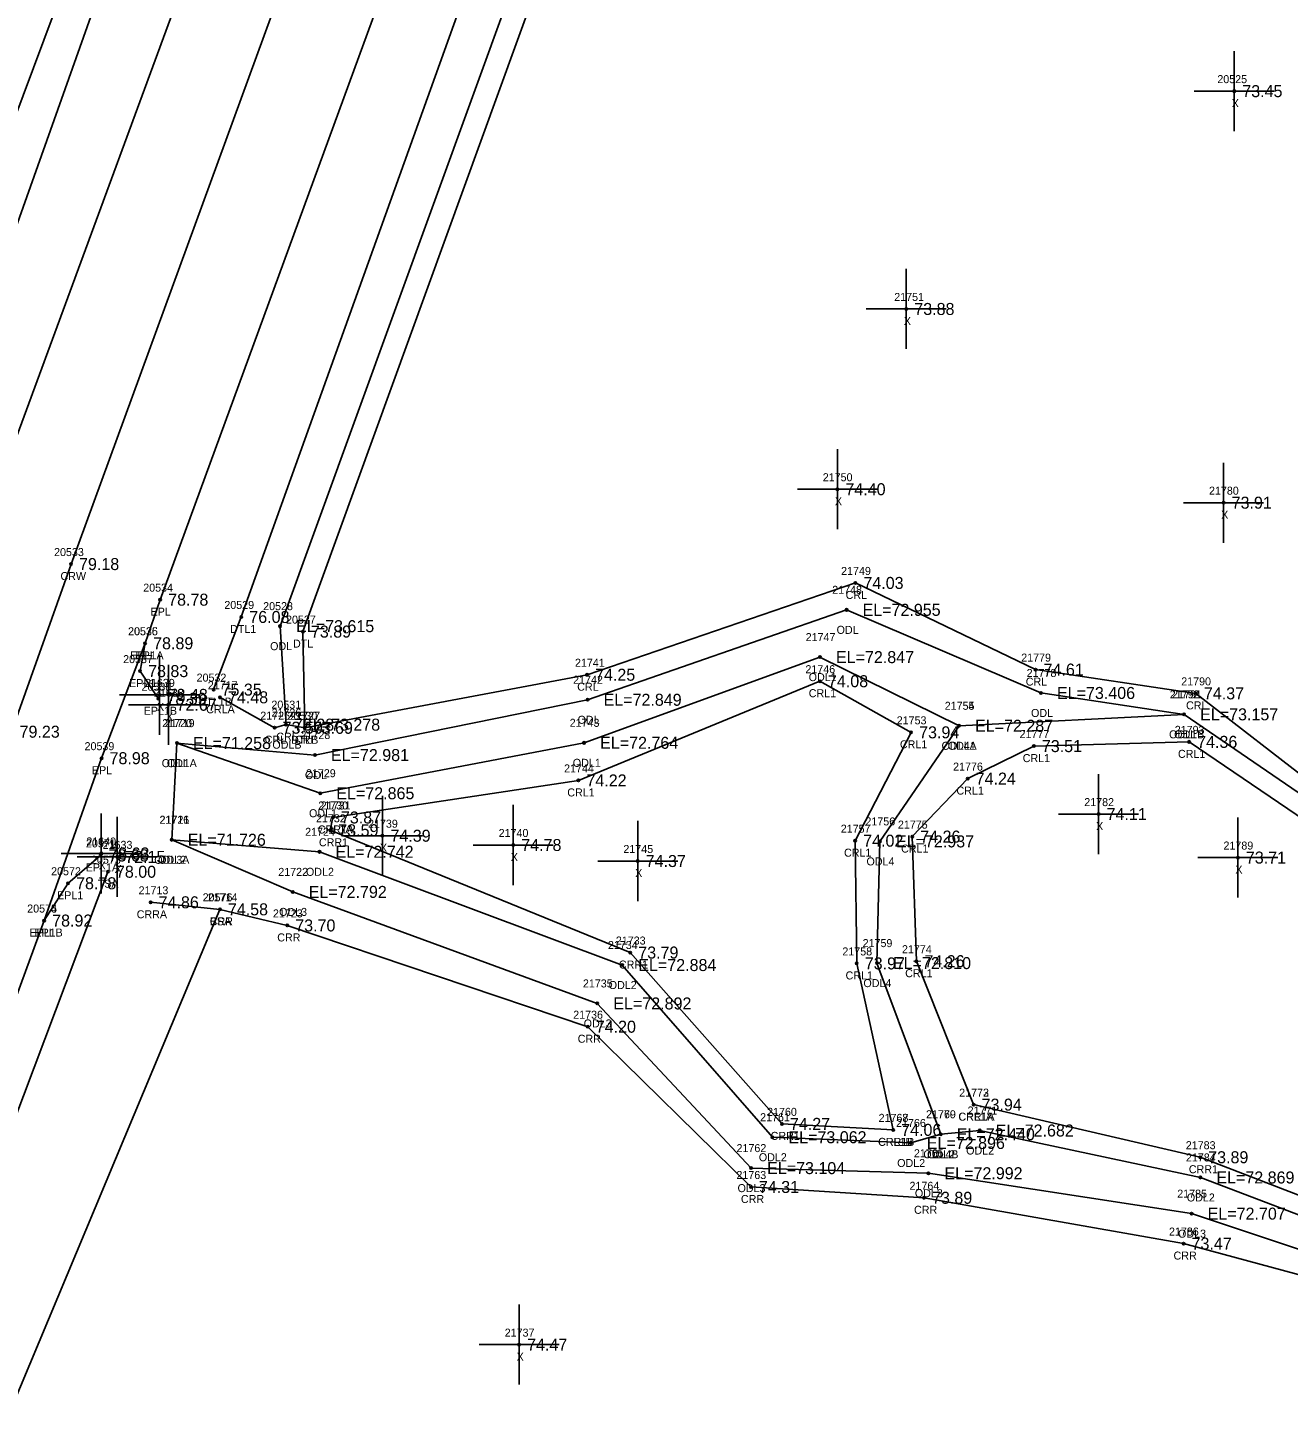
# Model space of a CAD drawing. Extents: x 2140110 to 2141565, y 506241 to 510327.
# Drawn here: x 2140964.5 to 2141122, y 508982.3 to 509154.8 of the extents above; entities that cross this region are included whole.
import ezdxf

# ---------------------------------------------------------------- set-up
doc = ezdxf.new("R2010")
doc.units = 0
for name, color, linetype in [('RD_DTM_BkLn1', 7, 'Continuous'), ('RD_DTM_BkLn2', 7, 'Continuous'), ('RD_DTM_BkLn_txCode', 7, 'Continuous'), ('RD_EX_H2O', 7, 'Continuous'), ('RD_EX_H2O_txCode', 7, 'Continuous'), ('RD_EX_Misc', 7, 'Continuous'), ('RD_EX_Misc_txCode', 7, 'Continuous'), ('RD_EX_Road', 7, 'Continuous'), ('RD_EX_Road_txCode', 7, 'Continuous'), ('RD_EX_TX_H2O_ELEV', 7, 'Continuous'), ('RD_EX_TX_Misc_ELEV', 7, 'Continuous'), ('RD_EX_TX_Road_ELEV', 7, 'Continuous'), ('RD_HC_Survey_ELEV', 7, 'Continuous'), ('RD_HC_Survey_txCode', 7, 'Continuous'), ('RD_SMD_Locator', 7, 'Continuous')]:
    doc.layers.add(name, color=color, linetype=linetype)

msp = doc.modelspace()

# ---------------------------------------------------------------- linework, layer by layer
at = {"layer": 'RD_DTM_BkLn1'}
msp.add_lwpolyline([(2141401.24, 510292.17), (2141386.62, 510241.55), (2141370.29, 510189.18), (2141352.34, 510135.64), (2141334.07, 510083.82), (2141314.82, 510031.25), (2141297.4, 509983.45), (2141260.01, 509880.66), (2141224.45, 509783.3), (2141187.1, 509681.41), (2141150.45, 509581.24), (2141112.96, 509478.26), (2141074.89, 509374.78), (2141038.89, 509276.46), (2141003.79, 509180.59), (2140969.89, 509087.8), (2140962.46, 509066.85), (2140921.91, 508956.12), (2140885.66, 508857.72), (2140850.55, 508762.05)], dxfattribs=at)
at = {"layer": 'RD_DTM_BkLn2'}
for points in [[(2140974.5, 509049.35), (2140937.76, 508951.84), (2140901.13, 508851.11), (2140867.71, 508755.37), (2140831.32, 508652.9), (2140795.63, 508558.35), (2140771.77, 508494.7), (2140759.99, 508454.23), (2140734.05, 508387.83)], [(2140988.49, 509044.65), (2140947.93, 508947.73), (2140912.71, 508846.53), (2140877.42, 508750.71), (2140841.6, 508647.73), (2140806.94, 508554.43), (2140782.47, 508491.27), (2140767.03, 508451.8), (2140743.6, 508391.1), (2140740.93, 508386.48)]]:
    msp.add_lwpolyline(points, dxfattribs=at)
at = {"layer": 'RD_EX_H2O'}
for points in [[(2141109.57, 509415.73), (2141114.37, 509420.62), (2141120.58, 509418.47), (2141123.73, 509414.72), (2141106.65, 509363.28), (2141087.87, 509318.68), (2141079.16, 509303.21), (2141069.29, 509273.89), (2141065.76, 509268.54), (2141032.31, 509171.57), (2140998.87, 509079.36), (2140999.1, 509067.34)], [(2141109.57, 509415.73), (2141094.19, 509368.74), (2141059.48, 509270.33), (2141024.5, 509174.17), (2140991.17, 509081.19), (2140987.7, 509072.11)], [(2141117.74, 509414.57), (2141100.21, 509366.33), (2141064.01, 509269.32), (2141029.63, 509172.59), (2140996.02, 509080.04), (2140996.76, 509067.73)], [(2141025.18, 509330), (2141033.42, 509326.19), (2141034.03, 509320.6), (2141020.74, 509281.87), (2140983.57, 509187.83), (2140949.44, 509091.79), (2140950.12, 509084.29)], [(2141028.31, 509323.95), (2141015.1, 509284.32), (2140979.54, 509188.24), (2140943.06, 509090.7)], [(2140988.5, 509071.15), (2140995.33, 509067.35), (2140996.76, 509067.73), (2140999.1, 509067.34), (2141034.38, 509073.97), (2141067.92, 509085.44), (2141090.44, 509074.61), (2141110.47, 509071.64), (2141125.77, 509059.81), (2141130.36, 509054.36)], [(2140983.12, 509065.42), (2141000.37, 509063.93), (2141034.44, 509070.84), (2141066.81, 509082.08), (2141091.11, 509071.69), (2141109, 509069.02), (2141130.36, 509054.36)], [(2140983.12, 509065.42), (2141001.04, 509059.16), (2141034.01, 509065.46), (2141063.49, 509076.17), (2141080.87, 509067.59), (2141109, 509069.02)], [(2141002.62, 509056.13), (2141033.3, 509060.76), (2141063.49, 509073.16), (2141074.88, 509066.77), (2141067.89, 509053.23), (2141068.09, 509037.89), (2141072.64, 509017.09)], [(2141080.87, 509067.59), (2141070.99, 509053.14), (2141070.61, 509037.93), (2141078.58, 509016.54)], [(2140983.12, 509065.42), (2140982.47, 509053.34), (2141000.94, 509051.84), (2141038.78, 509037.69), (2141057.55, 509016.17), (2141074.84, 509015.45), (2141078.58, 509016.54), (2141083.45, 509017.01), (2141111.03, 509011.14), (2141158.09, 508993.23), (2141163.15, 508993.34), (2141185.07, 509013.58), (2141188.28, 509016.58)], [(2141082.69, 509020.24), (2141075.54, 509038.17), (2141075.02, 509053.74), (2141081.95, 509060.99), (2141090.22, 509065.05), (2141109.63, 509065.58), (2141124.15, 509055.72), (2141130.36, 509054.36)], [(2141002.62, 509056.13), (2141002.29, 509054.53), (2141039.78, 509039.25), (2141058.74, 509017.84), (2141072.64, 509017.09)], [(2140982.47, 509053.34), (2140997.59, 509046.83), (2141035.66, 509032.89), (2141054.88, 509012.31), (2141077.05, 509011.67), (2141109.94, 509006.62), (2141157.44, 508990.81), (2141163.15, 508993.34)], [(2140979.84, 509045.53), (2140988.49, 509044.65), (2140996.91, 509042.64), (2141034.47, 509029.98), (2141054.86, 509009.95), (2141076.5, 509008.6), (2141108.93, 509002.88), (2141157.17, 508989.85), (2141167.48, 508991.01), (2141188.81, 509012.46), (2141188.28, 509016.58)], [(2141082.69, 509020.24), (2141111.01, 509013.67), (2141158.94, 508995.2), (2141180.37, 509014.56), (2141188.28, 509016.58)]]:
    msp.add_lwpolyline(points, dxfattribs=at)
at = {"layer": 'RD_EX_Misc'}
for p, q in [((2141115.27, 509141.9), (2141115.27, 509151.9)), ((2141110.27, 509146.9), (2141120.27, 509146.9)), ((2141074.28, 509114.68), (2141074.28, 509124.68)), ((2141069.28, 509119.68), (2141079.28, 509119.68)), ((2141065.67, 509092.15), (2141065.67, 509102.15)), ((2141113.94, 509090.47), (2141113.94, 509100.47)), ((2141060.67, 509097.15), (2141070.67, 509097.15)), ((2141108.94, 509095.47), (2141118.94, 509095.47)), ((2140980.96, 509066.45), (2140980.96, 509076.45)), ((2140982.07, 509065.22), (2140982.07, 509075.22)), ((2140975.96, 509071.45), (2140985.96, 509071.45)), ((2140977.07, 509070.22), (2140987.07, 509070.22)), ((2141098.31, 509051.55), (2141098.31, 509061.55)), ((2141008.81, 509048.85), (2141008.81, 509058.85)), ((2141025.16, 509047.69), (2141025.16, 509057.69)), ((2140973.66, 509046.63), (2140973.66, 509056.63)), ((2140975.66, 509046.21), (2140975.66, 509056.21)), ((2141093.31, 509056.55), (2141103.31, 509056.55)), ((2141115.72, 509046.12), (2141115.72, 509056.12)), ((2141040.71, 509045.69), (2141040.71, 509055.69)), ((2141003.81, 509053.85), (2141013.81, 509053.85)), ((2141020.16, 509052.69), (2141030.16, 509052.69)), ((2140968.66, 509051.63), (2140978.66, 509051.63)), ((2140970.66, 509051.21), (2140980.66, 509051.21)), ((2141110.72, 509051.12), (2141120.72, 509051.12)), ((2141035.71, 509050.69), (2141045.71, 509050.69)), ((2141025.89, 508985.25), (2141025.89, 508995.25)), ((2141020.89, 508990.25), (2141030.89, 508990.25))]:
    msp.add_line(p, q, dxfattribs=at)
at = {"layer": 'RD_EX_Road'}
for points in [[(2141175.93, 509686.04), (2141140.09, 509588.3), (2141106.08, 509494.11), (2141096.82, 509469.24), (2141063.82, 509378.98), (2141052.52, 509348.48), (2141043.48, 509323.88), (2141027.84, 509280.54), (2140992.95, 509184.87), (2140958.53, 509091.45), (2140950.8, 509069.47), (2140944.28, 509052.06), (2140911.45, 508962.1), (2140874.65, 508861.6), (2140839.42, 508765.22), (2140802.38, 508664.56)], [(2141197.99, 509676.56), (2141193.66, 509664.6), (2141161.61, 509577.24), (2141123.75, 509473.61), (2141115.5, 509450.65), (2141102.09, 509414.61), (2141086.27, 509371.27), (2141050.42, 509272.83), (2141015.08, 509176.39), (2140981.03, 509083.35), (2140979.15, 509077.9), (2140973.7, 509063.54), (2140966.53, 509043.25), (2140933.44, 508952.99), (2140896.92, 508852.59), (2140862.18, 508757.77)], [(2140979.15, 509077.9), (2140978.52, 509074.42), (2140980.81, 509070.97)], [(2140973.58, 509051.39), (2140969.52, 509047.91), (2140966.53, 509043.25)]]:
    msp.add_lwpolyline(points, dxfattribs=at)
at = {"layer": 'RD_SMD_Locator'}
for centre in [(2141115.27, 509146.9), (2141074.28, 509119.68), (2141065.67, 509097.15), (2141113.94, 509095.47), (2140969.89, 509087.8), (2141067.92, 509085.44), (2140981.03, 509083.35), (2141066.81, 509082.08), (2140991.17, 509081.19), (2140996.02, 509080.04), (2140998.87, 509079.36), (2140979.15, 509077.9), (2140979.15, 509077.9), (2141063.49, 509076.17), (2140978.52, 509074.42), (2141034.38, 509073.97), (2141063.49, 509073.16), (2141090.44, 509074.61), (2140980.96, 509071.45), (2140987.7, 509072.11), (2141091.11, 509071.69), (2141110.47, 509071.64), (2140980.81, 509070.97), (2140982.07, 509070.22), (2140988.5, 509071.15), (2141034.44, 509070.84), (2141109, 509069.02), (2141109, 509069.02), (2140995.33, 509067.35), (2140996.76, 509067.73), (2140996.76, 509067.73), (2140999.1, 509067.34), (2140999.1, 509067.34), (2141074.88, 509066.77), (2141080.87, 509067.59), (2141080.87, 509067.59), (2140983.12, 509065.42), (2140983.12, 509065.42), (2141034.01, 509065.46), (2141090.22, 509065.05), (2141109.63, 509065.58), (2140973.7, 509063.54), (2141000.37, 509063.93), (2141081.95, 509060.99), (2141033.3, 509060.76), (2141001.04, 509059.16), (2141002.62, 509056.13), (2141002.62, 509056.13), (2141098.31, 509056.55), (2141002.29, 509054.53), (2140982.47, 509053.34), (2140982.47, 509053.34), (2141008.81, 509053.85), (2141025.16, 509052.69), (2141067.89, 509053.23), (2141070.99, 509053.14), (2141075.02, 509053.74), (2140973.58, 509051.39), (2140973.66, 509051.63), (2140975.66, 509051.21), (2141000.94, 509051.84), (2141040.71, 509050.69), (2141115.72, 509051.12), (2140974.5, 509049.35), (2140969.52, 509047.91), (2140979.84, 509045.53), (2140997.59, 509046.83), (2140988.49, 509044.65), (2140988.49, 509044.65), (2140966.53, 509043.25), (2140966.53, 509043.25), (2140996.91, 509042.64), (2141039.78, 509039.25), (2141038.78, 509037.69), (2141068.09, 509037.89), (2141070.61, 509037.93), (2141075.54, 509038.17), (2141035.66, 509032.89), (2141034.47, 509029.98), (2141082.69, 509020.24), (2141082.69, 509020.24), (2141058.74, 509017.84), (2141057.55, 509016.17), (2141072.64, 509017.09), (2141072.64, 509017.09), (2141078.58, 509016.54), (2141078.58, 509016.54), (2141083.45, 509017.01), (2141074.84, 509015.45), (2141111.01, 509013.67), (2141054.88, 509012.31), (2141077.05, 509011.67), (2141111.03, 509011.14), (2141054.86, 509009.95), (2141076.5, 509008.6), (2141109.94, 509006.62), (2141108.93, 509002.88), (2141025.89, 508990.25)]:
    msp.add_circle(centre, 0.15, dxfattribs=at)

# ---------------------------------------------------------------- texts
at = {"layer": 'RD_DTM_BkLn_txCode'}
for s, p in [('20573', (2140972.38, 509050.35)), ('TSA', (2140973.22, 509047.35)), ('20576', (2140986.34, 509045.65)), ('BSA', (2140987.22, 509042.65))]:
    msp.add_text(s, height=1, dxfattribs=at).set_placement(p)
at = {"layer": 'RD_EX_H2O_txCode'}
for s, p in [('21749', (2141066.13, 509086.44)), ('21748', (2141065.02, 509084.08)), ('CRL', (2141066.7, 509083.44)), ('20529', (2140989.05, 509082.19)), ('20528', (2140993.9, 509082.04)), ('DTL1', (2140989.76, 509079.19)), ('20527', (2140996.76, 509080.36)), ('ODL', (2141065.57, 509079.08)), ('DTL', (2140997.63, 509077.36)), ('21747', (2141061.7, 509078.17)), ('ODL', (2140994.77, 509077.04)), ('21779', (2141088.64, 509075.61)), ('21741', (2141032.87, 509074.97)), ('21746', (2141061.67, 509074.16)), ('20532', (2140985.58, 509073.11)), ('21717', (2140986.98, 509072.15)), ('21742', (2141032.64, 509072.84)), ('ODL1', (2141062.08, 509073.17)), ('CRL', (2141089.21, 509072.61)), ('21778', (2141089.32, 509073.69)), ('21790', (2141108.64, 509072.64)), ('CRL', (2141033.15, 509071.97)), ('CRL1', (2141062.09, 509071.16)), ('21792', (2141107.21, 509071.02)), ('21791', (2141107.49, 509071.02)), ('DTL1B', (2140985.82, 509070.11)), ('CRLA', (2140986.78, 509069.15)), ('20531', (2140994.93, 509069.73)), ('21726', (2140994.95, 509068.73)), ('21754', (2141079.08, 509069.59)), ('21755', (2141079.08, 509069.59)), ('CRL', (2141109.24, 509069.64)), ('21720', (2140981.28, 509067.42)), ('21719', (2140981.61, 509067.42)), ('21725', (2140993.54, 509068.35)), ('20530', (2140996.94, 509068.34)), ('21727', (2140997.3, 509068.34)), ('21743', (2141032.21, 509067.46)), ('ODL', (2141033.2, 509067.84)), ('21753', (2141073.08, 509067.77)), ('ODL', (2141089.87, 509068.69)), ('CRL', (2140994.1, 509065.35)), ('CRL', (2140995.54, 509065.73)), ('DTLB', (2140997.38, 509065.34)), ('CRL', (2140997.87, 509065.34)), ('21728', (2140998.57, 509065.93)), ('21777', (2141088.43, 509066.05)), ('ODL1B', (2141107.12, 509066.02)), ('ODL', (2141107.76, 509066.02)), ('21793', (2141107.83, 509066.58)), ('ODLB', (2140995.05, 509064.73)), ('CRL1', (2141073.48, 509064.77)), ('ODL4A', (2141078.69, 509064.59)), ('ODL1', (2141079.47, 509064.59)), ('CRL1', (2141108.23, 509063.58)), ('ODL1A', (2140981.22, 509062.42)), ('ODL', (2140981.87, 509062.42)), ('ODL1', (2141032.6, 509062.46)), ('21776', (2141080.13, 509061.99)), ('CRL1', (2141088.83, 509063.05)), ('ODL', (2140999.12, 509060.93)), ('21729', (2140999.25, 509061.16)), ('21744', (2141031.51, 509061.76)), ('CRL1', (2141031.91, 509058.76)), ('CRL1', (2141080.55, 509058.99)), ('21730', (2141000.79, 509057.13)), ('21731', (2141001.11, 509057.13)), ('21716', (2140980.93, 509055.34)), ('21721', (2140980.96, 509055.34)), ('ODL1', (2140999.63, 509056.16)), ('21732', (2141000.5, 509055.53)), ('21756', (2141069.17, 509055.14)), ('21724', (2140999.15, 509053.84)), ('CRR1A', (2141000.72, 509054.13)), ('CRL1A', (2141000.74, 509054.13)), ('21757', (2141066.09, 509054.23)), ('21775', (2141073.23, 509054.74)), ('CRR1', (2141000.87, 509052.53)), ('CRL1', (2141073.63, 509051.74)), ('ODL3A', (2140980.29, 509050.34)), ('ODL2', (2140980.78, 509050.34)), ('CRL1', (2141066.5, 509051.23)), ('ODL4', (2141069.3, 509050.14)), ('21722', (2140995.79, 509048.83)), ('ODL2', (2140999.25, 509048.84)), ('21713', (2140978.33, 509046.53)), ('21714', (2140986.97, 509045.65)), ('CRRA', (2140978.1, 509043.53)), ('21723', (2140995.12, 509043.64)), ('ODL3', (2140995.89, 509043.83)), ('CRR', (2140987.23, 509042.65)), ('CRR', (2140995.66, 509040.64)), ('21734', (2141036.99, 509039.69)), ('21733', (2141037.98, 509040.25)), ('21759', (2141068.82, 509039.93)), ('21758', (2141066.29, 509038.89)), ('21774', (2141073.74, 509039.17)), ('CRR1', (2141038.36, 509037.25)), ('CRL1', (2141074.14, 509036.17)), ('21735', (2141033.86, 509034.89)), ('ODL2', (2141037.09, 509034.69)), ('CRL1', (2141066.69, 509035.89)), ('ODL4', (2141068.92, 509034.93)), ('21736', (2141032.65, 509030.98)), ('ODL3', (2141033.96, 509029.89)), ('CRR', (2141033.21, 509027.98)), ('21772', (2141080.89, 509021.24)), ('21773', (2141080.89, 509021.24)), ('21760', (2141056.88, 509018.84)), ('21771', (2141081.94, 509019.01)), ('21761', (2141056.01, 509018.17)), ('21767', (2141070.82, 509018.09)), ('21768', (2141070.82, 509018.09)), ('21766', (2141073, 509017.45)), ('21770', (2141076.74, 509018.54)), ('21769', (2141076.76, 509018.54)), ('CRR1A', (2141080.78, 509018.24)), ('CRL1A', (2141080.81, 509018.24)), ('CRR1', (2141057.32, 509015.84)), ('21762', (2141053.06, 509014.31)), ('CRR1B', (2141070.75, 509015.09)), ('CRL1B', (2141070.77, 509015.09)), ('21765', (2141075.23, 509013.67)), ('ODL4B', (2141076.41, 509013.54)), ('ODL2', (2141076.88, 509013.54)), ('ODL2', (2141081.76, 509014.01)), ('21783', (2141109.21, 509014.67)), ('ODL2', (2141055.85, 509013.17)), ('ODL2', (2141073.14, 509012.45)), ('21784', (2141109.23, 509013.14)), ('21763', (2141053.05, 509010.95)), ('CRR1', (2141109.59, 509011.67)), ('ODL3', (2141053.19, 509009.31)), ('21764', (2141074.68, 509009.6)), ('ODL3', (2141075.35, 509008.67)), ('21785', (2141108.14, 509008.62)), ('CRR', (2141053.61, 509007.95)), ('CRR', (2141075.25, 509006.6)), ('ODL2', (2141109.34, 509008.14)), ('21786', (2141107.11, 509003.88)), ('ODL3', (2141108.24, 509003.62)), ('CRR', (2141107.68, 509000.88))]:
    msp.add_text(s, height=1, dxfattribs=at).set_placement(p)
at = {"layer": 'RD_EX_Misc_txCode'}
for s, p in [('20525', (2141113.15, 509147.9)), ('X', (2141114.95, 509144.9)), ('21751', (2141072.77, 509120.68)), ('X', (2141073.97, 509117.68)), ('21750', (2141063.84, 509098.15)), ('21780', (2141112.11, 509096.47)), ('X', (2141065.36, 509095.15)), ('X', (2141113.63, 509093.47)), ('21639', (2140979.14, 509072.45)), ('21638', (2140980.25, 509071.22)), ('X', (2140980.64, 509069.45)), ('X', (2140981.75, 509068.22)), ('21782', (2141096.52, 509057.55)), ('21739', (2141007.01, 509054.85)), ('21740', (2141023.33, 509053.69)), ('X', (2141098, 509054.55)), ('21640', (2140971.8, 509052.63)), ('21633', (2140973.84, 509052.21)), ('X', (2141008.49, 509051.85)), ('21745', (2141038.92, 509051.69)), ('21789', (2141113.92, 509052.12)), ('X', (2141024.85, 509050.69)), ('X', (2140973.34, 509049.63)), ('X', (2140975.34, 509049.21)), ('X', (2141040.4, 509048.69)), ('X', (2141115.4, 509049.12)), ('21737', (2141024.09, 508991.25)), ('X', (2141025.58, 508988.25))]:
    msp.add_text(s, height=1, dxfattribs=at).set_placement(p)
at = {"layer": 'RD_EX_Road_txCode'}
for s, p in [('20534', (2140978.91, 509084.35)), ('EPL', (2140979.83, 509081.35)), ('20536', (2140977.01, 509078.9)), ('20535', (2140977.03, 509078.9)), ('EPL1A', (2140977.29, 509075.9)), ('EPL', (2140977.95, 509075.9)), ('20537', (2140976.4, 509075.42)), ('EPL1', (2140977.15, 509072.42)), ('20538', (2140978.7, 509071.97)), ('EPL1B', (2140978.97, 509068.97)), ('20539', (2140971.58, 509064.54)), ('EPL', (2140972.5, 509061.54)), ('20571', (2140971.75, 509052.39)), ('20572', (2140967.4, 509048.91)), ('EPL1A', (2140971.73, 509049.39)), ('EPL1', (2140968.15, 509045.91)), ('20574', (2140964.41, 509044.25)), ('20575', (2140964.41, 509044.25)), ('EPL1B', (2140964.69, 509041.25)), ('EPL', (2140965.32, 509041.25))]:
    msp.add_text(s, height=1, dxfattribs=at).set_placement(p)
at = {"layer": 'RD_EX_TX_H2O_ELEV'}
for s, p in [('74.03', (2141068.92, 509084.69)), ('76.08', (2140992.17, 509080.44)), ('EL=72.955', (2141068.81, 509081.33)), ('EL=73.615', (2140998.02, 509079.29)), ('73.89', (2140999.87, 509078.61)), ('EL=72.847', (2141065.49, 509075.42)), ('74.61', (2141091.44, 509073.86)), ('74.25', (2141035.38, 509073.22)), ('74.08', (2141064.49, 509072.41)), ('75.35', (2140988.7, 509071.36)), ('74.48', (2140989.5, 509070.4)), ('EL=72.849', (2141036.44, 509070.09)), ('EL=73.406', (2141093.11, 509070.94)), ('74.37', (2141111.47, 509070.89)), ('EL=73.157', (2141111, 509068.27)), ('EL=73.157', (2141111, 509068.27)), ('73.50', (2140996.33, 509066.6)), ('73.28', (2140997.76, 509066.98)), ('EL=73.278', (2140998.76, 509066.98)), ('73.69', (2141000.1, 509066.59)), ('73.69', (2141000.1, 509066.59)), ('EL=72.287', (2141082.87, 509066.84)), ('EL=72.287', (2141082.87, 509066.84)), ('73.94', (2141075.88, 509066.02)), ('74.36', (2141110.63, 509064.83)), ('EL=71.258', (2140985.12, 509064.67)), ('EL=71.258', (2140985.12, 509064.67)), ('EL=72.981', (2141002.37, 509063.18)), ('EL=72.764', (2141036.01, 509064.71)), ('73.51', (2141091.22, 509064.3)), ('74.22', (2141034.3, 509060.01)), ('74.24', (2141082.95, 509060.24)), ('EL=72.865', (2141003.04, 509058.41)), ('73.87', (2141003.62, 509055.38)), ('73.87', (2141003.62, 509055.38)), ('73.59', (2141003.29, 509053.78)), ('74.26', (2141076.02, 509052.99)), ('EL=71.726', (2140984.47, 509052.59)), ('EL=71.726', (2140984.47, 509052.59)), ('EL=72.742', (2141002.94, 509051.09)), ('74.02', (2141068.89, 509052.48)), ('EL=72.937', (2141072.99, 509052.39)), ('EL=72.792', (2140999.59, 509046.08)), ('74.86', (2140980.84, 509044.78)), ('74.58', (2140989.49, 509043.9)), ('73.70', (2140997.91, 509041.89)), ('73.79', (2141040.78, 509038.5)), ('73.97', (2141069.09, 509037.14)), ('EL=72.810', (2141072.61, 509037.18)), ('74.26', (2141076.54, 509037.42)), ('EL=72.884', (2141040.78, 509036.94)), ('EL=72.892', (2141037.66, 509032.14)), ('74.20', (2141035.47, 509029.23)), ('73.94', (2141083.69, 509019.49)), ('73.94', (2141083.69, 509019.49)), ('74.27', (2141059.74, 509017.09)), ('EL=73.062', (2141059.55, 509015.42)), ('74.06', (2141073.64, 509016.34)), ('74.06', (2141073.64, 509016.34)), ('EL=72.896', (2141076.84, 509014.7)), ('EL=72.440', (2141080.58, 509015.79)), ('EL=72.440', (2141080.58, 509015.79)), ('EL=72.682', (2141085.45, 509016.26)), ('EL=73.104', (2141056.88, 509011.56)), ('73.89', (2141112.01, 509012.92)), ('EL=72.992', (2141079.05, 509010.92)), ('EL=72.869', (2141113.03, 509010.39)), ('74.31', (2141055.86, 509009.2)), ('73.89', (2141077.5, 509007.85)), ('EL=72.707', (2141111.94, 509005.87)), ('73.47', (2141109.93, 509002.13))]:
    msp.add_text(s, height=1.5, dxfattribs=at).set_placement(p)
at = {"layer": 'RD_EX_TX_Misc_ELEV'}
for s, p in [('73.45', (2141116.27, 509146.15)), ('73.88', (2141075.28, 509118.93)), ('74.40', (2141066.67, 509096.4)), ('73.91', (2141114.94, 509094.72)), ('78.48', (2140981.96, 509070.7)), ('72.67', (2140983.07, 509069.47)), ('74.11', (2141099.31, 509055.8)), ('74.39', (2141009.81, 509053.1)), ('74.78', (2141026.16, 509051.94)), ('78.63', (2140974.66, 509050.88)), ('72.15', (2140976.66, 509050.46)), ('74.37', (2141041.71, 509049.94)), ('73.71', (2141116.72, 509050.37)), ('78.00', (2140975.5, 509048.6)), ('74.58', (2140989.49, 509043.9)), ('74.47', (2141026.89, 508989.5))]:
    msp.add_text(s, height=1.5, dxfattribs=at).set_placement(p)
at = {"layer": 'RD_EX_TX_Road_ELEV'}
for s, p in [('78.78', (2140982.03, 509082.6)), ('78.89', (2140980.15, 509077.15)), ('78.89', (2140980.15, 509077.15)), ('78.83', (2140979.52, 509073.67)), ('78.39', (2140981.81, 509070.22)), ('78.98', (2140974.7, 509062.79)), ('78.68', (2140974.58, 509050.64)), ('78.78', (2140970.52, 509047.16)), ('78.92', (2140967.53, 509042.5)), ('78.92', (2140967.53, 509042.5))]:
    msp.add_text(s, height=1.5, dxfattribs=at).set_placement(p)
at = {"layer": 'RD_HC_Survey_ELEV'}
for s, p in [('79.18', (2140970.89, 509087.05)), ('79.23', (2140963.46, 509066.1))]:
    msp.add_text(s, height=1.5, dxfattribs=at).set_placement(p)
at = {"layer": 'RD_HC_Survey_txCode'}
for s, p in [('20533', (2140967.77, 509088.8)), ('CRW', (2140968.57, 509085.8))]:
    msp.add_text(s, height=1, dxfattribs=at).set_placement(p)

doc.saveas('drawing.dxf')
